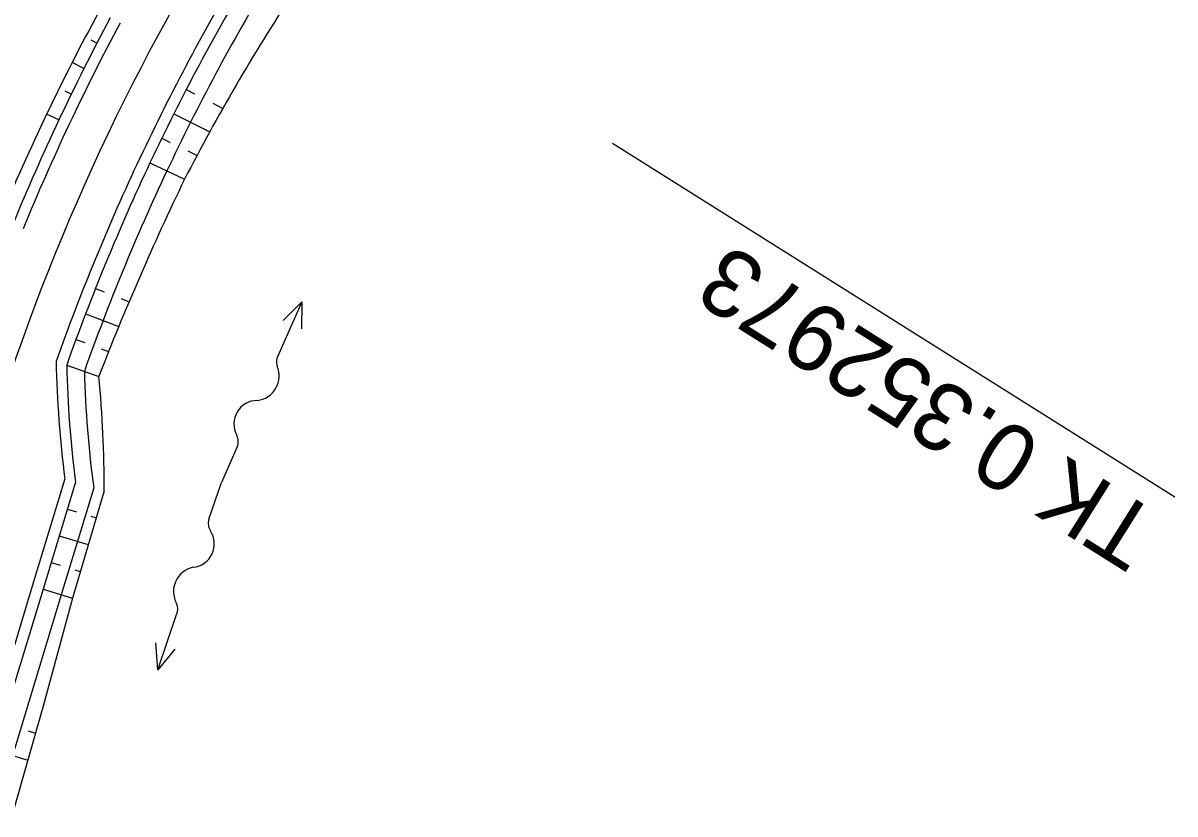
# Model space of a CAD drawing. Extents: x -481645 to -478728, y -1113199 to -1110710.
# Drawn here: x -479575.4 to -479524, y -1112726.4 to -1112691.1 of the extents above; entities that cross this region are included whole.
import ezdxf

# ---------------------------------------------------------------- set-up
doc = ezdxf.new("R2010")
doc.units = 0
for name, color, linetype in [('CP14_HECTOMETRY', 7, 'Continuous'), ('CP14_HLBODY', 7, 'Continuous'), ('CP14_HRANA_TELESO', 7, 'Continuous'), ('CP14_PRIKOP', 7, 'Continuous'), ('CP1_HATCH_SLOPE_R', 7, 'Continuous'), ('CP1_HLBODY', 7, 'Continuous'), ('CP1_HRANA_TELESO', 7, 'Continuous'), ('CP1_OSA', 7, 'Continuous'), ('CP1_STANICENI', 7, 'Continuous'), ('CP1_VOZOVKA', 7, 'Continuous'), ('CP1_ZPEVKRAJ', 7, 'Continuous')]:
    doc.layers.add(name, color=color, linetype=linetype)

# ---------------------------------------------------------------- blocks, each defined once
blk = doc.blocks.new('A$C70B')
at = {"layer": 'CP14_HLBODY'}
for p, q in [((0.869, 0.002), (-0.869, -0.002)), ((6.861, 0.426), (7.971, -0.002)), ((7.971, -0.002), (5.275, -0.002)), ((7.971, -0.002), (6.862, -0.478))]:
    blk.add_line(p, q, dxfattribs=at)
for centre, radius, start, end in [((2.168, -0.416), 1.055, 24.4039, 142.0836), ((0.872, 0.584), 0.582, 269.6924, 322.7901), ((4.08, 0.589), 1.109, 210.8873, 317.3707), ((5.319, -0.636), 0.636, 85.9766, 131.7248)]:
    blk.add_arc(centre, radius, start, end, dxfattribs=at)

msp = doc.modelspace()

# ---------------------------------------------------------------- linework, layer by layer
at = {"layer": 'CP14_HRANA_TELESO'}
for p, q in [((-479568.149, -1112694.017), (-479567.778, -1112694.21)), ((-479566.962, -1112694.633), (-479566.517, -1112694.863)), ((-479568.705, -1112695.106), (-479567.1, -1112695.912)), ((-479569.247, -1112696.201), (-479568.87, -1112696.384)), ((-479568.082, -1112696.768), (-479567.67, -1112696.969)), ((-479569.775, -1112697.303), (-479568.227, -1112698.033)), ((-479572.207, -1112702.906), (-479571.818, -1112703.06)), ((-479571.067, -1112703.359), (-479570.706, -1112703.503)), ((-479572.651, -1112704.044), (-479571.171, -1112704.611)), ((-479573.081, -1112705.188), (-479572.688, -1112705.333)), ((-479571.958, -1112705.602), (-479571.622, -1112705.726)), ((-479573.496, -1112706.337), (-479572.06, -1112706.846)), ((-479573.466, -1112712.767), (-479573.059, -1112712.89)), ((-479572.415, -1112713.086), (-479572.178, -1112713.158)), ((-479573.828, -1112713.963), (-479572.532, -1112714.357)), ((-479574.191, -1112715.16), (-479573.784, -1112715.284)), ((-479573.132, -1112715.481), (-479572.887, -1112715.555)), ((-479574.554, -1112716.356), (-479573.241, -1112716.754)), ((-479575.222, -1112722.684), (-479574.889, -1112722.785)), ((-479576.731, -1112723.533), (-479575.23, -1112723.988))]:
    msp.add_line(p, q, dxfattribs=at)
at = {"layer": 'CP14_PRIKOP'}
for p, q in [((-479572.663, -1112691.678), (-479572.663, -1112691.678)), ((-479572.144, -1112691.947), (-479572.404, -1112691.812)), ((-479572.725, -1112693.085), (-479573.254, -1112692.819)), ((-479573.831, -1112693.968), (-479573.831, -1112693.968)), ((-479573.292, -1112694.23), (-479573.562, -1112694.099)), ((-479573.845, -1112695.383), (-479574.394, -1112695.124))]:
    msp.add_line(p, q, dxfattribs=at)
at = {"layer": 'CP1_HATCH_SLOPE_R'}
msp.add_line((-479523.956, -1112712.241), (-479549.104, -1112696.44), dxfattribs=at)
at = {"layer": 'CP1_HLBODY'}
for p, q in [((-479573.581, -1112711.426), (-479575.032, -1112716.211)), ((-479575.032, -1112716.211), (-479576.484, -1112720.995))]:
    msp.add_line(p, q, dxfattribs=at)
for centre, radius, start, end in [((-479481.366, -1112739.002), 98.25, 149.01874, 151.88353), ((-479481.366, -1112739.002), 101.75, 151.88353, 154.74832), ((-479481.366, -1112739.002), 98.25, 151.88353, 154.74832), ((-479481.366, -1112739.002), 101.75, 154.74832, 157.61311), ((-479481.366, -1112739.002), 98.25, 154.74832, 157.61311), ((-479481.366, -1112739.002), 98.25, 157.61311, 160.4779), ((-479524.852, -1112705.204), 49.125, 181.1271, 187.2766)]:
    msp.add_arc(centre, radius, start, end, dxfattribs=at)
at = {"layer": 'CP1_HRANA_TELESO'}
for p, q in [((-479571.823, -1112711.959), (-479573.241, -1112716.754)), ((-479573.241, -1112716.754), (-479574.548, -1112721.583)), ((-479574.548, -1112721.583), (-479575.912, -1112726.394))]:
    msp.add_line(p, q, dxfattribs=at)
for centre, radius, start, end in [((-479483.185, -1112742.076), 95.78, 146.88158, 149.74836), ((-479481.642, -1112739.549), 102.842, 151.54244, 154.40728), ((-479482.933, -1112741.989), 95.954, 149.86945, 152.73601), ((-479481.554, -1112739.428), 102.869, 154.48923, 157.35405), ((-479481.909, -1112740.21), 96.071, 153.95856, 156.82362), ((-479482.265, -1112741.266), 96.165, 156.16196, 159.02767), ((-479619.935, -1112711.626), 48.113, 359.6032, 5.7011)]:
    msp.add_arc(centre, radius, start, end, dxfattribs=at)
at = {"layer": 'CP1_OSA'}
msp.add_arc((-479481.366, -1112739.002), 100, 147.85753, 163.12732, dxfattribs=at)
at = {"layer": 'CP1_STANICENI'}
for p, q in [((-479573.581, -1112711.426), (-479575.032, -1112716.211)), ((-479575.032, -1112716.211), (-479576.484, -1112720.995))]:
    msp.add_line(p, q, dxfattribs=at)
for centre, radius, start, end in [((-479481.366, -1112739.002), 98.25, 149.01874, 151.88353), ((-479481.366, -1112739.002), 101.75, 151.88353, 154.74832), ((-479481.366, -1112739.002), 98.25, 151.88353, 154.74832), ((-479481.366, -1112739.002), 101.75, 154.74832, 157.61311), ((-479481.366, -1112739.002), 98.25, 154.74832, 157.61311), ((-479481.366, -1112739.002), 98.25, 157.61311, 160.4779), ((-479524.852, -1112705.204), 49.125, 181.1271, 187.2766)]:
    msp.add_arc(centre, radius, start, end, dxfattribs=at)
at = {"layer": 'CP1_VOZOVKA'}
for p, q in [((-479573.103, -1112711.571), (-479574.554, -1112716.356)), ((-479574.554, -1112716.356), (-479576.005, -1112721.141))]:
    msp.add_line(p, q, dxfattribs=at)
for centre, radius, start, end in [((-479481.366, -1112739.002), 97.75, 149.01874, 151.88353), ((-479481.366, -1112739.002), 102.25, 151.88353, 154.74832), ((-479481.366, -1112739.002), 97.75, 151.88353, 154.74832), ((-479481.366, -1112739.002), 102.25, 154.74832, 157.61311), ((-479481.366, -1112739.002), 97.75, 154.74832, 157.61311), ((-479481.366, -1112739.002), 97.75, 157.61311, 160.4779), ((-479524.632, -1112705.297), 48.875, 181.2201, 187.3759)]:
    msp.add_arc(centre, radius, start, end, dxfattribs=at)
at = {"layer": 'CP1_ZPEVKRAJ'}
for p, q in [((-479572.289, -1112711.818), (-479573.74, -1112716.603)), ((-479573.74, -1112716.603), (-479575.191, -1112721.387)), ((-479575.191, -1112721.387), (-479576.642, -1112726.172))]:
    msp.add_line(p, q, dxfattribs=at)
for centre, radius, start, end in [((-479481.366, -1112739.002), 96.912, 149.01874, 151.88353), ((-479481.366, -1112739.002), 96.912, 151.88353, 154.74832), ((-479481.366, -1112739.002), 96.912, 154.74832, 157.61311), ((-479481.366, -1112739.002), 96.912, 157.61311, 160.4779), ((-479524.267, -1112705.342), 48.456, 181.5075, 187.6799)]:
    msp.add_arc(centre, radius, start, end, dxfattribs=at)

# ---------------------------------------------------------------- block references
at = {"layer": 'CP14_HECTOMETRY'}
for p, rotation in [((-479566.229, -1112710.784), 65.97796761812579), ((-479566.859, -1112712.402), -108.74310621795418)]:
    msp.add_blockref('A$C70B', p, dxfattribs=dict(at, rotation=rotation))

# ---------------------------------------------------------------- texts
at = {"layer": 'CP1_HATCH_SLOPE_R'}
msp.add_text('TK 0.352973', height=3, rotation=147.8575, dxfattribs=at).set_placement((-479524.487, -1112713.089))

doc.saveas('drawing.dxf')
